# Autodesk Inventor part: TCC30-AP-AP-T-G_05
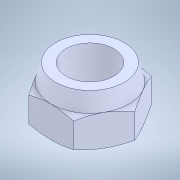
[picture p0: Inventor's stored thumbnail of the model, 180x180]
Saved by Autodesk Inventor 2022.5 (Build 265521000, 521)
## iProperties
Created: 2023-09
Part Number: TCC30-AP-AP-T-G_05
Material: 一般
Document SubType Name: Modeling
Designer: ImaoCorp
Density: 1 g/cm^3
Appearance: 既定
Author: ImaoCorp
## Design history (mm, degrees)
feature "TCC30-AP-AP-T-G_05"
node "ソリッド1"
